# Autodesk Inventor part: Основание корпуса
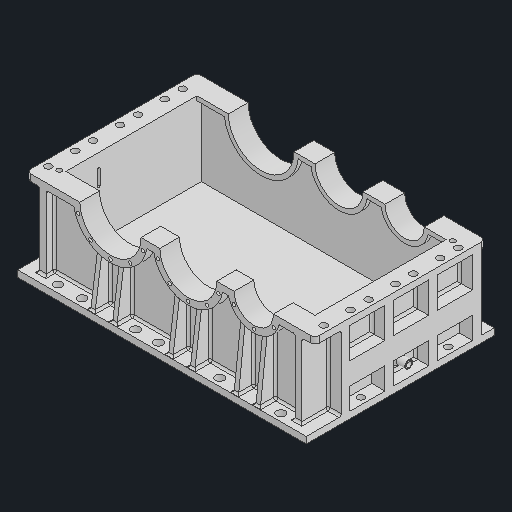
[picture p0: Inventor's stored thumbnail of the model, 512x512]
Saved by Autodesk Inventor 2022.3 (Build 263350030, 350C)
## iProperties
Created: 2020-09
Part Number: Основание корпуса
Material: Сталь, легированная
Document SubType Name: Modeling
Designer: Карташов
Density: 7.73 g/cm^3
Appearance: По умолчанию
Title: D:\мои документы\Ирина\_WorldSkills\2020_09 ФНЧ\Module A\GIVEN\Основание корпуса.stp
Author: Дом
Sending System: Autodesk Inventor 2021
Preprocessor: ST-DEVELOPER v18.1
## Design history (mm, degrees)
feature "Твердое тело2"
node "Твердое тело1"
